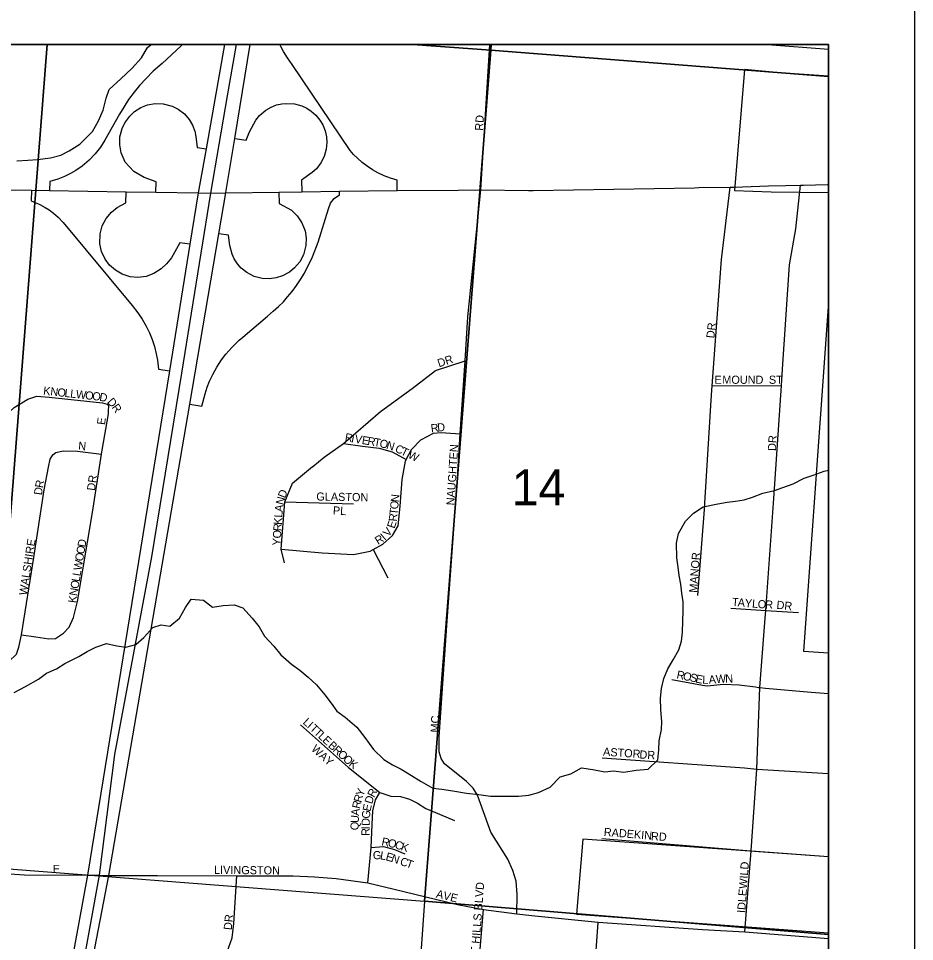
# Model space of a CAD drawing. Extents: x 0 to 34, y 0 to 22.
# Drawn here: x 8.457 to 9.5, y 19.857 to 20.93 of the extents above; entities that cross this region are included whole.
import ezdxf

# ---------------------------------------------------------------- set-up
doc = ezdxf.new("R2010")
doc.units = 0
for name, color, linetype in [('GM_X_City_Street', 7, 'Continuous'), ('GM_X_City_Street_Text', 7, 'Continuous'), ('GM_X_Corporation', 7, 'Continuous'), ('GM_X_Interchange_Ramps', 7, 'Continuous'), ('GM_X_Interstate_Route', 7, 'Continuous'), ('GM_X_Minor_River', 7, 'Continuous'), ('GM_X_Section', 7, 'Continuous'), ('GM_X_Section_Text', 7, 'Continuous'), ('GM_X_Township', 7, 'Continuous'), ('GM_X_US_Route', 7, 'Continuous'), ('SH_Data', 7, 'Continuous')]:
    doc.layers.add(name, color=color, linetype=linetype)

msp = doc.modelspace()

# ---------------------------------------------------------------- linework, layer by layer
at = {"layer": 'GM_X_City_Street'}
for points in [[(8.9954, 20.7309), (9.0057, 20.9)], [(9.3287, 20.9), (9.4, 20.8945)], [(9.2558, 20.3647), (9.256, 20.3664), (9.2637, 20.4924), (9.2645, 20.5029), (9.2755, 20.6498), (9.2856, 20.7341)], [(9.3097, 19.9621), (9.3164, 20.0569), (9.3199, 20.152), (9.3262, 20.2328), (9.3268, 20.2416), (9.3363, 20.3717), (9.3452, 20.5033), (9.3465, 20.5223), (9.3546, 20.6437), (9.3619, 20.6854), (9.3671, 20.7364)], [(9.0373, 19.8886), (9.0377, 19.9114), (9.0365, 19.9267), (9.0327, 19.9392), (9.0266, 19.9522), (9.0068, 19.9838), (8.9916, 20.0269), (8.9863, 20.0349), (8.9787, 20.0426), (8.9531, 20.0632), (8.9493, 20.0693), (8.9467, 20.0773), (8.9468, 20.0948), (8.9562, 20.2296), (8.9676, 20.3898), (8.9714, 20.4472), (8.9769, 20.532), (8.9803, 20.5831), (8.9954, 20.7309)], [(8.7996, 20.4092), (8.7997, 20.4093), (8.8131, 20.4201), (8.8354, 20.4357), (8.8787, 20.4729), (8.9155, 20.5), (8.9427, 20.5208), (8.9769, 20.532)], [(9.2645, 20.5029), (9.3452, 20.5033)], [(8.4292, 20.4569), (8.4523, 20.4777), (8.468, 20.4876), (8.4786, 20.4908), (8.493, 20.4897), (8.5552, 20.4832), (8.5605, 20.4815), (8.5623, 20.4792)], [(8.4609, 20.2133), (8.4775, 20.2111), (8.4926, 20.2085), (8.5002, 20.2091), (8.5098, 20.2154), (8.5163, 20.2224), (8.5215, 20.2333), (8.526, 20.2522), (8.5436, 20.3555), (8.5538, 20.4236), (8.5545, 20.4281), (8.5621, 20.4705), (8.5622, 20.4739), (8.5623, 20.4792)], [(8.763, 20.3131), (8.8107, 20.3088), (8.847, 20.3069), (8.8667, 20.3105), (8.8702, 20.3125), (8.8812, 20.3187), (8.8926, 20.3288), (8.8992, 20.3401), (8.9013, 20.3629), (8.9039, 20.394), (8.9075, 20.4152), (8.9086, 20.4173), (8.9145, 20.4288), (8.9255, 20.4401), (8.9404, 20.4479), (8.9491, 20.4486), (8.9714, 20.4472)], [(8.8354, 20.4357), (8.8577, 20.4328), (8.877, 20.4303), (8.8921, 20.426), (8.9086, 20.4173)], [(8.4609, 20.2133), (8.4752, 20.3034), (8.487, 20.3821), (8.4921, 20.4085), (8.4942, 20.4176), (8.4973, 20.4225), (8.5007, 20.4254), (8.5091, 20.4275), (8.5261, 20.4268), (8.5538, 20.4236)], [(8.7668, 20.2969), (8.763, 20.3131), (8.7674, 20.3681), (8.7763, 20.3897), (8.7971, 20.4073), (8.7996, 20.4092)], [(8.7674, 20.3681), (8.8472, 20.3657)], [(9.2477, 20.259), (9.2558, 20.3643), (9.2558, 20.3647)], [(8.8702, 20.3125), (8.8872, 20.2795)], [(9.2861, 20.2442), (9.3268, 20.2416), (9.3648, 20.2392)], [(8.2723, 20.1367), (8.2714, 20.131), (8.2765, 20.1199), (8.2828, 20.1145), (8.2925, 20.1097), (8.3039, 20.1099), (8.3171, 20.1107), (8.3469, 20.1261), (8.3893, 20.1491), (8.4053, 20.1552), (8.4341, 20.1733), (8.446, 20.1821), (8.4548, 20.1907), (8.4576, 20.199), (8.4609, 20.2133)], [(9.2176, 20.1614), (9.2531, 20.1546), (9.2587, 20.1541), (9.2777, 20.1558), (9.2958, 20.1553), (9.315, 20.1527), (9.3185, 20.1522)], [(9.3185, 20.1522), (9.3199, 20.152), (9.3265, 20.1511), (9.3798, 20.1468), (9.4, 20.1449)], [(8.7855, 20.1085), (8.8415, 20.0589), (8.8777, 20.0299), (8.8906, 20.0257), (8.9017, 20.0254), (8.9123, 20.0223), (8.9215, 20.0174), (8.9314, 20.0113), (8.9398, 20.0078), (8.9646, 19.9973)], [(9.1364, 20.0703), (9.3021, 20.0585), (9.3023, 20.0585)], [(9.3023, 20.0585), (9.3164, 20.0569), (9.4, 20.0519)], [(8.8639, 19.9248), (8.8678, 19.9659), (8.8689, 19.9926), (8.8697, 20.0086), (8.8727, 20.0212), (8.8777, 20.0299)], [(9.1363, 19.9765), (9.3049, 19.9625)], [(8.0837, 19.9634), (8.1845, 19.9557), (8.3733, 19.9405), (8.4117, 19.9375), (8.4643, 19.9343), (8.5377, 19.9336), (8.551, 19.9336), (8.5626, 19.9333), (8.6189, 19.9334), (8.7115, 19.9328)], [(8.8678, 19.9659), (8.8819, 19.9671), (8.8948, 19.9636), (8.907, 19.9587)], [(9.3026, 19.8678), (9.3097, 19.9621)], [(9.3049, 19.9625), (9.3097, 19.9621), (9.4, 19.9554)], [(8.5949, 19.4144), (8.5759, 19.4488), (8.5611, 19.4943), (8.5542, 19.5428), (8.554, 19.5971), (8.5619, 19.6719), (8.5709, 19.7029), (8.5821, 19.7241), (8.6001, 19.744), (8.6041, 19.7477), (8.6246, 19.7665), (8.6651, 19.8049), (8.6925, 19.8284), (8.7001, 19.8444), (8.7058, 19.8608), (8.7077, 19.8775), (8.7115, 19.9328)], [(8.7115, 19.9328), (8.7771, 19.9328), (8.8018, 19.932), (8.827, 19.9297), (8.8639, 19.9248), (8.8944, 19.9175), (8.968, 19.8996), (8.9984, 19.8939), (9.0373, 19.8886), (9.0583, 19.8863), (9.1317, 19.8791), (9.2534, 19.8707), (9.3026, 19.8678), (9.4, 19.8601)], [(8.9904, 19.7964), (8.9984, 19.8939)], [(8.6925, 19.8284), (8.7211, 19.8124), (8.7557, 19.799), (8.7809, 19.7937), (8.811, 19.791), (8.8422, 19.7941), (8.878, 19.7964), (8.9146, 19.7987), (8.9543, 19.7975), (8.9904, 19.7964), (9.0289, 19.7922), (9.0609, 19.7922), (9.0865, 19.7971), (9.1002, 19.8017), (9.1139, 19.8108), (9.1242, 19.8242), (9.1295, 19.8463), (9.1317, 19.8791)]]:
    msp.add_lwpolyline(points, dxfattribs=at)
at = {"layer": 'GM_X_Corporation'}
for p, q in [((9.4, 20.7279), (9.4, 20.8632)), ((9.4, 20.1924), (9.4, 20.6003)), ((9.4, 19.8666), (9.4, 19.9549))]:
    msp.add_line(p, q, dxfattribs=at)
for points in [[(9.4, 20.8632), (9.3432, 20.8671), (9.3021, 20.8709), (9.2906, 20.7303), (9.3333, 20.7284), (9.4, 20.7279)], [(9.4, 20.6003), (9.3708, 20.1945), (9.4, 20.1924)], [(9.4, 19.9549), (9.1141, 19.9755), (9.1067, 19.8884), (9.4, 19.8666)]]:
    msp.add_lwpolyline(points, dxfattribs=at)
at = {"layer": 'GM_X_Interchange_Ramps'}
for points in [[(8.4436, 19.5593), (8.4661, 19.5999), (8.4914, 19.6555), (8.5156, 19.7229), (8.5318, 19.7777), (8.5421, 19.8286), (8.5626, 19.9333), (8.6565, 20.4816), (8.6904, 20.6796), (8.6986, 20.7273), (8.6987, 20.7277), (8.709, 20.7908), (8.7268, 20.9)], [(8.697, 20.9), (8.6755, 20.7785), (8.6665, 20.7273), (8.6568, 20.6676), (8.6329, 20.5203), (8.5377, 19.9336), (8.5174, 19.8236), (8.5019, 19.7544), (8.4814, 19.6904), (8.4719, 19.663), (8.4476, 19.6063)], [(8.6482, 20.9), (8.6467, 20.8985), (8.6245, 20.878), (8.6142, 20.8689), (8.6058, 20.8606), (8.598, 20.8521), (8.5919, 20.8446), (8.5854, 20.8359), (8.5797, 20.8272), (8.5747, 20.8188), (8.5577, 20.7888), (8.5526, 20.7807), (8.5466, 20.7729), (8.5397, 20.7656), (8.5313, 20.7585), (8.5242, 20.7535), (8.518, 20.7499), (8.5109, 20.7464), (8.5032, 20.7434), (8.4936, 20.7406), (8.4934, 20.7302)], [(8.8981, 20.7301), (8.8978, 20.7423), (8.8902, 20.7445), (8.8827, 20.7473), (8.8756, 20.7506), (8.8693, 20.7542), (8.8631, 20.7583), (8.8572, 20.7628), (8.8518, 20.7676), (8.8472, 20.7722), (8.8433, 20.7768), (8.7756, 20.8767), (8.7702, 20.8844), (8.7657, 20.892), (8.7627, 20.8976), (8.7616, 20.9)], [(8.6171, 20.7281), (8.6174, 20.7403), (8.6037, 20.7454), (8.5916, 20.7523), (8.5814, 20.7632), (8.5769, 20.774), (8.5752, 20.7834), (8.5754, 20.7924), (8.5778, 20.8022), (8.5809, 20.8089), (8.5867, 20.8168), (8.5924, 20.8221), (8.5998, 20.8267), (8.6074, 20.8296), (8.6163, 20.8312), (8.6258, 20.8309), (8.6362, 20.8282), (8.6431, 20.8247), (8.6503, 20.8192), (8.6559, 20.8127), (8.6599, 20.806), (8.6625, 20.7991), (8.6638, 20.7931), (8.6652, 20.7801), (8.6755, 20.7785)], [(8.709, 20.7908), (8.7221, 20.7888), (8.7261, 20.7982), (8.7333, 20.8118), (8.7377, 20.8173), (8.7451, 20.8236), (8.7512, 20.8271), (8.7577, 20.8297), (8.7637, 20.831), (8.7697, 20.8315), (8.7785, 20.8309), (8.787, 20.8285), (8.7928, 20.8258), (8.7979, 20.8225), (8.8033, 20.8177), (8.808, 20.812), (8.8113, 20.8065), (8.814, 20.7995), (8.8156, 20.7926), (8.816, 20.7858), (8.8153, 20.7783), (8.8129, 20.7697), (8.8092, 20.7623), (8.8039, 20.7554), (8.7992, 20.751), (8.7866, 20.7423), (8.787, 20.7285)], [(8.4725, 20.7306), (8.4722, 20.7183), (8.4822, 20.7138), (8.4882, 20.7105), (8.4928, 20.7075), (8.4979, 20.7038), (8.5034, 20.699), (8.5092, 20.6929), (8.5896, 20.5964), (8.5962, 20.588), (8.6013, 20.5803), (8.6059, 20.5722), (8.6096, 20.5645), (8.6127, 20.5569), (8.6154, 20.5486), (8.6175, 20.5403), (8.619, 20.5328), (8.6202, 20.5224), (8.6329, 20.5203)], [(8.6568, 20.6676), (8.6452, 20.6693), (8.6352, 20.6519), (8.6295, 20.645), (8.6233, 20.6389), (8.6148, 20.6335), (8.6057, 20.6303), (8.5963, 20.6291), (8.5872, 20.6299), (8.5778, 20.6329), (8.57, 20.6374), (8.5632, 20.6434), (8.5581, 20.6503), (8.554, 20.6591), (8.552, 20.6682), (8.5522, 20.6797), (8.5548, 20.6891), (8.5593, 20.6976), (8.5655, 20.705), (8.5722, 20.7102), (8.5822, 20.7157), (8.5825, 20.7287)], [(8.6565, 20.4816), (8.6705, 20.4792), (8.6744, 20.4938), (8.6769, 20.5012), (8.6797, 20.5083), (8.6835, 20.5161), (8.6882, 20.5246), (8.6937, 20.533), (8.6987, 20.5396), (8.7057, 20.5477), (8.7141, 20.5559), (8.7182, 20.5594), (8.7469, 20.5839), (8.7538, 20.5896), (8.76, 20.5953), (8.7655, 20.6008), (8.7705, 20.6064), (8.7756, 20.6126), (8.7809, 20.6197), (8.7855, 20.6266), (8.79, 20.6341), (8.7994, 20.6528), (8.806, 20.6699), (8.8179, 20.7088), (8.8205, 20.7155), (8.8246, 20.7207), (8.8308, 20.7251), (8.8307, 20.7292)], [(8.7602, 20.7282), (8.7606, 20.7149), (8.7751, 20.7074), (8.7817, 20.7008), (8.7872, 20.6925), (8.7907, 20.6831), (8.7921, 20.6748), (8.7917, 20.666), (8.7889, 20.6554), (8.7845, 20.6471), (8.7786, 20.64), (8.7728, 20.6353), (8.7646, 20.6308), (8.757, 20.6284), (8.7489, 20.6274), (8.7409, 20.6279), (8.7317, 20.6303), (8.7232, 20.6346), (8.7166, 20.6398), (8.7122, 20.6447), (8.7083, 20.6507), (8.7058, 20.6562), (8.7032, 20.6662), (8.7016, 20.678), (8.6904, 20.6796)]]:
    msp.add_lwpolyline(points, dxfattribs=at)
at = {"layer": 'GM_X_Interstate_Route'}
for points in [[(8.7107, 20.9), (8.7, 20.8402), (8.6809, 20.727)], [(8.6809, 20.727), (8.6471, 20.5176), (8.6121, 20.3042), (8.5692, 20.0743), (8.551, 19.9336), (8.5296, 19.8139), (8.5082, 19.7315), (8.4785, 19.6541), (8.4423, 19.575), (8.3822, 19.4765), (8.3443, 19.4226), (8.2928, 19.3608), (8.2434, 19.3078)]]:
    msp.add_lwpolyline(points, dxfattribs=at)
at = {"layer": 'GM_X_Minor_River'}
for points in [[(8.4555, 20.7647), (8.468, 20.7654), (8.4793, 20.7661), (8.4944, 20.7683), (8.5066, 20.7713), (8.5164, 20.7761), (8.5286, 20.784), (8.5434, 20.7987), (8.5503, 20.8112), (8.5557, 20.8237), (8.5592, 20.8374), (8.563, 20.8476), (8.5763, 20.86), (8.5892, 20.8721), (8.6003, 20.8845), (8.6075, 20.8963), (8.6116, 20.9)], [(9.2055, 20.1031), (9.2059, 20.1126), (9.2048, 20.1259), (9.2045, 20.1396), (9.2057, 20.1509), (9.2081, 20.1627), (9.2131, 20.1737), (9.2192, 20.1843), (9.2257, 20.196), (9.2288, 20.2058), (9.23, 20.2165), (9.2309, 20.2415), (9.2306, 20.2518), (9.2291, 20.2616), (9.228, 20.2723), (9.2262, 20.2825), (9.2248, 20.292), (9.2233, 20.303), (9.223, 20.3201), (9.2254, 20.3311), (9.2334, 20.3455), (9.2429, 20.3549), (9.2539, 20.3621), (9.271, 20.3658), (9.282, 20.3676), (9.2918, 20.3687), (9.3016, 20.3705), (9.3115, 20.3735), (9.3236, 20.378), (9.3372, 20.3813), (9.3467, 20.3846), (9.3589, 20.3891), (9.3717, 20.3955), (9.382, 20.3989), (9.3949, 20.4037), (9.4, 20.4049)], [(8.4521, 20.1461), (8.4653, 20.1532), (8.4805, 20.1619), (8.49, 20.1686), (8.5014, 20.1739), (8.5113, 20.1799), (8.5276, 20.1881), (8.5374, 20.1938), (8.5473, 20.199), (8.5598, 20.2031), (8.5719, 20.2004), (8.5821, 20.1988), (8.5938, 20.2021), (8.6033, 20.2101), (8.6136, 20.2218), (8.6235, 20.2251), (8.6333, 20.2235), (8.6447, 20.2326), (8.6516, 20.2451), (8.6584, 20.2549), (8.6724, 20.2537), (8.683, 20.2456), (8.6955, 20.2475), (8.7083, 20.2481), (8.7185, 20.2447), (8.7294, 20.2328), (8.7373, 20.2225), (8.7436, 20.2119), (8.7545, 20.2), (8.7624, 20.1901), (8.7748, 20.179), (8.7846, 20.1721), (8.7944, 20.1641), (8.8042, 20.1553), (8.8139, 20.1435), (8.8211, 20.1339), (8.8278, 20.1244), (8.8376, 20.1175), (8.8511, 20.1061), (8.8605, 20.0938), (8.8703, 20.0801), (8.8823, 20.0683), (8.8925, 20.0621), (8.9026, 20.0571), (8.9147, 20.0495), (8.926, 20.0426), (8.9396, 20.0349), (8.9498, 20.0337), (8.9626, 20.0317), (8.9785, 20.029), (8.9928, 20.0277), (9.0064, 20.0258), (9.039, 20.0256), (9.0511, 20.027), (9.0624, 20.03), (9.0761, 20.036), (9.0875, 20.048), (9.1, 20.0518), (9.1125, 20.0585), (9.1258, 20.0565), (9.1397, 20.0538), (9.1496, 20.0553), (9.1617, 20.0537), (9.176, 20.0558), (9.19, 20.0569), (9.2011, 20.0678), (9.2023, 20.0796), (9.2027, 20.0902), (9.2055, 20.1031)]]:
    msp.add_lwpolyline(points, dxfattribs=at)
at = {"layer": 'GM_X_Section'}
for p, q in [((8.4907, 20.9), (7.9844, 20.9)), ((8.9162, 20.9), (8.4907, 20.9)), ((9.0075, 20.9), (8.9162, 20.9)), ((9.4, 19.8649), (9.4, 20.8627)), ((9.4, 19.2334), (9.4, 19.8649))]:
    msp.add_line(p, q, dxfattribs=at)
for points in [[(7.9844, 20.9), (7.911, 19.983), (8.4159, 19.9436), (8.4907, 20.9)], [(8.4907, 20.9), (8.4159, 19.9436), (8.9298, 19.9037), (9.007, 20.8932), (8.9162, 20.9)], [(8.9162, 20.9), (9.007, 20.8932), (9.0075, 20.9)], [(9.0075, 20.9), (9.007, 20.8932), (9.4, 20.8627)], [(9.4, 20.8627), (9.4, 20.9), (9.0075, 20.9)], [(9.4, 20.8627), (9.007, 20.8932), (8.9298, 19.9037), (9.4, 19.8649)], [(9.4, 19.8649), (8.9298, 19.9037), (8.8584, 18.8902), (9.3728, 18.8467), (9.4, 19.2334)]]:
    msp.add_lwpolyline(points, dxfattribs=at)
msp.add_lwpolyline([(8.4159, 19.9436), (8.9298, 19.9037), (8.8584, 18.8902), (8.3382, 18.9328)], close=True, dxfattribs=at)
at = {"layer": 'GM_X_Township'}
msp.add_lwpolyline([(9.4, 17.8295), (9.4, 20.9), (4.4299, 20.9)], dxfattribs=at)
at = {"layer": 'GM_X_US_Route'}
for points in [[(9.0562, 20.7302), (9.2439, 20.7334), (9.249, 20.7335)], [(9.249, 20.7335), (9.2856, 20.7341), (9.2896, 20.7342)], [(9.2896, 20.7342), (9.3302, 20.7354)], [(9.3302, 20.7354), (9.3504, 20.7359)], [(9.3504, 20.7359), (9.3671, 20.7364), (9.3707, 20.7365)], [(9.3707, 20.7365), (9.3987, 20.7371), (9.4, 20.7371)], [(8.3444, 20.7307), (8.3953, 20.7314), (8.4725, 20.7306), (8.4934, 20.7302), (8.5825, 20.7287), (8.6171, 20.7281), (8.6665, 20.7273), (8.6809, 20.727)], [(8.6809, 20.727), (8.6986, 20.7273), (8.7602, 20.7282), (8.787, 20.7285), (8.8307, 20.7292), (8.8981, 20.7301), (8.9689, 20.7307)], [(8.9689, 20.7307), (8.9954, 20.7309), (9.0508, 20.7301), (9.0562, 20.7302)]]:
    msp.add_lwpolyline(points, dxfattribs=at)
at = {"layer": 'SH_Data'}
for p, q in [((9.5, 21), (9.5, 14)), ((2.6, 20.9), (9.4, 20.9)), ((9.4, 20.9), (9.4, 14.1))]:
    msp.add_line(p, q, dxfattribs=at)

# ---------------------------------------------------------------- texts
at = {"layer": 'GM_X_City_Street_Text'}
for s, rotation, p in [('RD', 86.989, (8.9979, 20.7995)), ('DR', 83.9934, (9.267, 20.5579)), ('DR', 18.4386, (8.9466, 20.5244)), ('E', 0, (9.2671, 20.5053)), ('MOUND', 0, (9.2763, 20.5053)), ('ST', 0, (9.3305, 20.5053)), ('K', 353.7805, (8.4857, 20.4928)), ('N', 353.785, (8.494, 20.4919)), ('O', 353.7805, (8.5022, 20.491)), ('L', 353.7902, (8.5105, 20.4901)), ('L', 353.7594, (8.5171, 20.4894)), ('W', 353.7884, (8.5238, 20.4887)), ('O', 353.7805, (8.5345, 20.4875)), ('O', 353.785, (8.5428, 20.4866)), ('D', 349.6717, (8.5509, 20.4857)), ('D', 312.1708, (8.5599, 20.4838)), ('R', 304.795, (8.5653, 20.4779)), ('E', 82.8783, (8.5579, 20.4571)), ('R', 8.0168, (8.9377, 20.4486)), ('D', 4.4188, (8.9449, 20.4497)), ('R', 350.6814, (8.8366, 20.4387)), ('I', 350.7206, (8.844, 20.4374)), ('V', 350.6922, (8.8481, 20.4368)), ('E', 350.6993, (8.8563, 20.4354)), ('R', 350.6814, (8.8629, 20.4343)), ('DR', 86.989, (9.3387, 20.427)), ('N', 354.8074, (8.5265, 20.4287)), ('T', 349.8955, (8.8703, 20.4331)), ('O', 345.7994, (8.8767, 20.432)), ('N', 342.8507, (8.8846, 20.43)), ('C', 334.8907, (8.8946, 20.4267)), ('NAUGHTEN', 86.2839, (8.9645, 20.3637)), ('T', 334.0703, (8.9013, 20.4236)), ('W', 334.0614, (8.9096, 20.4196)), ('R', 79.6712, (8.4857, 20.3836)), ('DR', 82.1508, (8.5462, 20.3805)), ('D', 81.7988, (8.4845, 20.3754)), ('D', 68.7575, (8.7675, 20.3716)), ('GLASTON', 359.1191, (8.8038, 20.3695)), ('N', 75.8248, (8.7656, 20.3638)), ('O', 84.2029, (8.8989, 20.359)), ('N', 84.1763, (8.8998, 20.3673)), ('A', 82.8921, (8.7646, 20.3559)), ('PL', 356.4262, (8.8229, 20.3534)), ('T', 84.173, (8.8983, 20.3524)), ('K', 86.4258, (8.7637, 20.341)), ('L', 86.4258, (8.7642, 20.3494)), ('E', 71.5716, (8.8948, 20.3364)), ('R', 83.5474, (8.8974, 20.3448)), ('R', 86.4258, (8.7632, 20.3336)), ('V', 50.5424, (8.8877, 20.3267)), ('Y', 86.4258, (8.7622, 20.3169)), ('O', 86.4258, (8.7627, 20.3252)), ('R', 32.2011, (8.8757, 20.3178)), ('I', 40.4682, (8.8833, 20.3227)), ('WALSHIRE', 81.1948, (8.4671, 20.2588)), ('O', 80.4454, (8.5337, 20.3066)), ('D', 80.4478, (8.5351, 20.3148)), ('O', 80.4263, (8.5323, 20.2984)), ('MANOR', 85.6039, (9.247, 20.262)), ('W', 80.4409, (8.5305, 20.2877)), ('L', 80.4461, (8.5294, 20.2811)), ('O', 80.4478, (8.5269, 20.2663)), ('L', 80.4209, (8.5283, 20.2745)), ('N', 80.5377, (8.5256, 20.2581)), ('K', 82.6364, (8.5245, 20.2499)), ('T', 355.3771, (9.2873, 20.247)), ('A', 355.3616, (9.2939, 20.2465)), ('Y', 355.3531, (9.3022, 20.2458)), ('L', 355.3665, (9.3106, 20.2451)), ('O', 355.3616, (9.3172, 20.2446)), ('R', 358.4975, (9.3261, 20.2439)), ('DR', 353.9946, (9.339, 20.2437)), ('R', 347.9663, (9.2225, 20.1628)), ('O', 347.9709, (9.2299, 20.1612)), ('S', 347.972, (9.238, 20.1595)), ('E', 347.972, (9.2445, 20.1581)), ('L', 358.2981, (9.2529, 20.1565)), ('A', 5.0179, (9.2608, 20.1563)), ('W', 3.7861, (9.269, 20.1571)), ('N', 0.4591, (9.2797, 20.1578)), ('L', 317.2798, (8.7875, 20.1107)), ('I', 317.2589, (8.7924, 20.1062)), ('MC', 87.3992, (8.9462, 20.0995)), ('T', 317.2817, (8.7955, 20.1034)), ('T', 317.2798, (8.8004, 20.0988)), ('L', 317.264, (8.8053, 20.0943)), ('E', 317.2817, (8.8102, 20.0898)), ('B', 317.2887, (8.8169, 20.0836)), ('WAY', 317.4929, (8.7973, 20.0795)), ('R', 317.2673, (8.8224, 20.0785)), ('O', 317.2947, (8.8279, 20.0734)), ('ASTOR', 356.2708, (9.1373, 20.0728)), ('DR', 356.9884, (9.1797, 20.0695)), ('O', 317.4387, (8.8341, 20.0677)), ('K', 322.4404, (8.8409, 20.0615)), ('Y', 68.6612, (8.8581, 20.0246)), ('R', 74.2614, (8.8561, 20.0176)), ('D', 72.7333, (8.8687, 20.0159)), ('R', 62.1204, (8.871, 20.0234)), ('R', 76.3701, (8.8544, 20.0104)), ('E', 77.9453, (8.8668, 20.0072)), ('U', 86.939, (8.8532, 19.9943)), ('A', 84.5286, (8.8536, 20.0025)), ('G', 85.1202, (8.8661, 19.9992)), ('Q', 89.3879, (8.8531, 19.986)), ('D', 88.12, (8.8659, 19.991)), ('R', 89.9271, (8.8658, 19.9794)), ('I', 89.4319, (8.8658, 19.9869)), ('RADEKIN', 355.3916, (9.1381, 19.9795)), ('RD', 356.989, (9.1931, 19.9745)), ('R', 347.99, (8.8792, 19.9686)), ('O', 347.2839, (8.8865, 19.9671)), ('C', 343.0472, (8.8944, 19.9653)), ('K', 341.6342, (8.9015, 19.9631)), ('G', 359.0382, (8.8696, 19.9524)), ('L', 351.1666, (8.8776, 19.9523)), ('E', 344.7113, (8.8839, 19.9513)), ('N', 341.2886, (8.8902, 19.9496)), ('C', 340.5128, (8.9004, 19.9461)), ('T', 340.4675, (8.9075, 19.9436)), ('E', 0, (8.4971, 19.9362)), ('LIVINGSTON', 359.3856, (8.6848, 19.9353)), ('IDLEWILD', 85.7938, (9.3029, 19.8895)), ('WALNUT HILLS BLVD', 85.6311, (8.9895, 19.797)), ('AVE', 346.4293, (8.9426, 19.9078)), ('DR', 84.5611, (8.7054, 19.8696))]:
    msp.add_text(s, height=0.00947, rotation=rotation, dxfattribs=at).set_placement(p)
at = {"layer": 'GM_X_Section_Text'}
msp.add_text('14', height=0.04186, rotation=0, dxfattribs=at).set_placement((9.0313, 20.3639))

doc.saveas('drawing.dxf')
